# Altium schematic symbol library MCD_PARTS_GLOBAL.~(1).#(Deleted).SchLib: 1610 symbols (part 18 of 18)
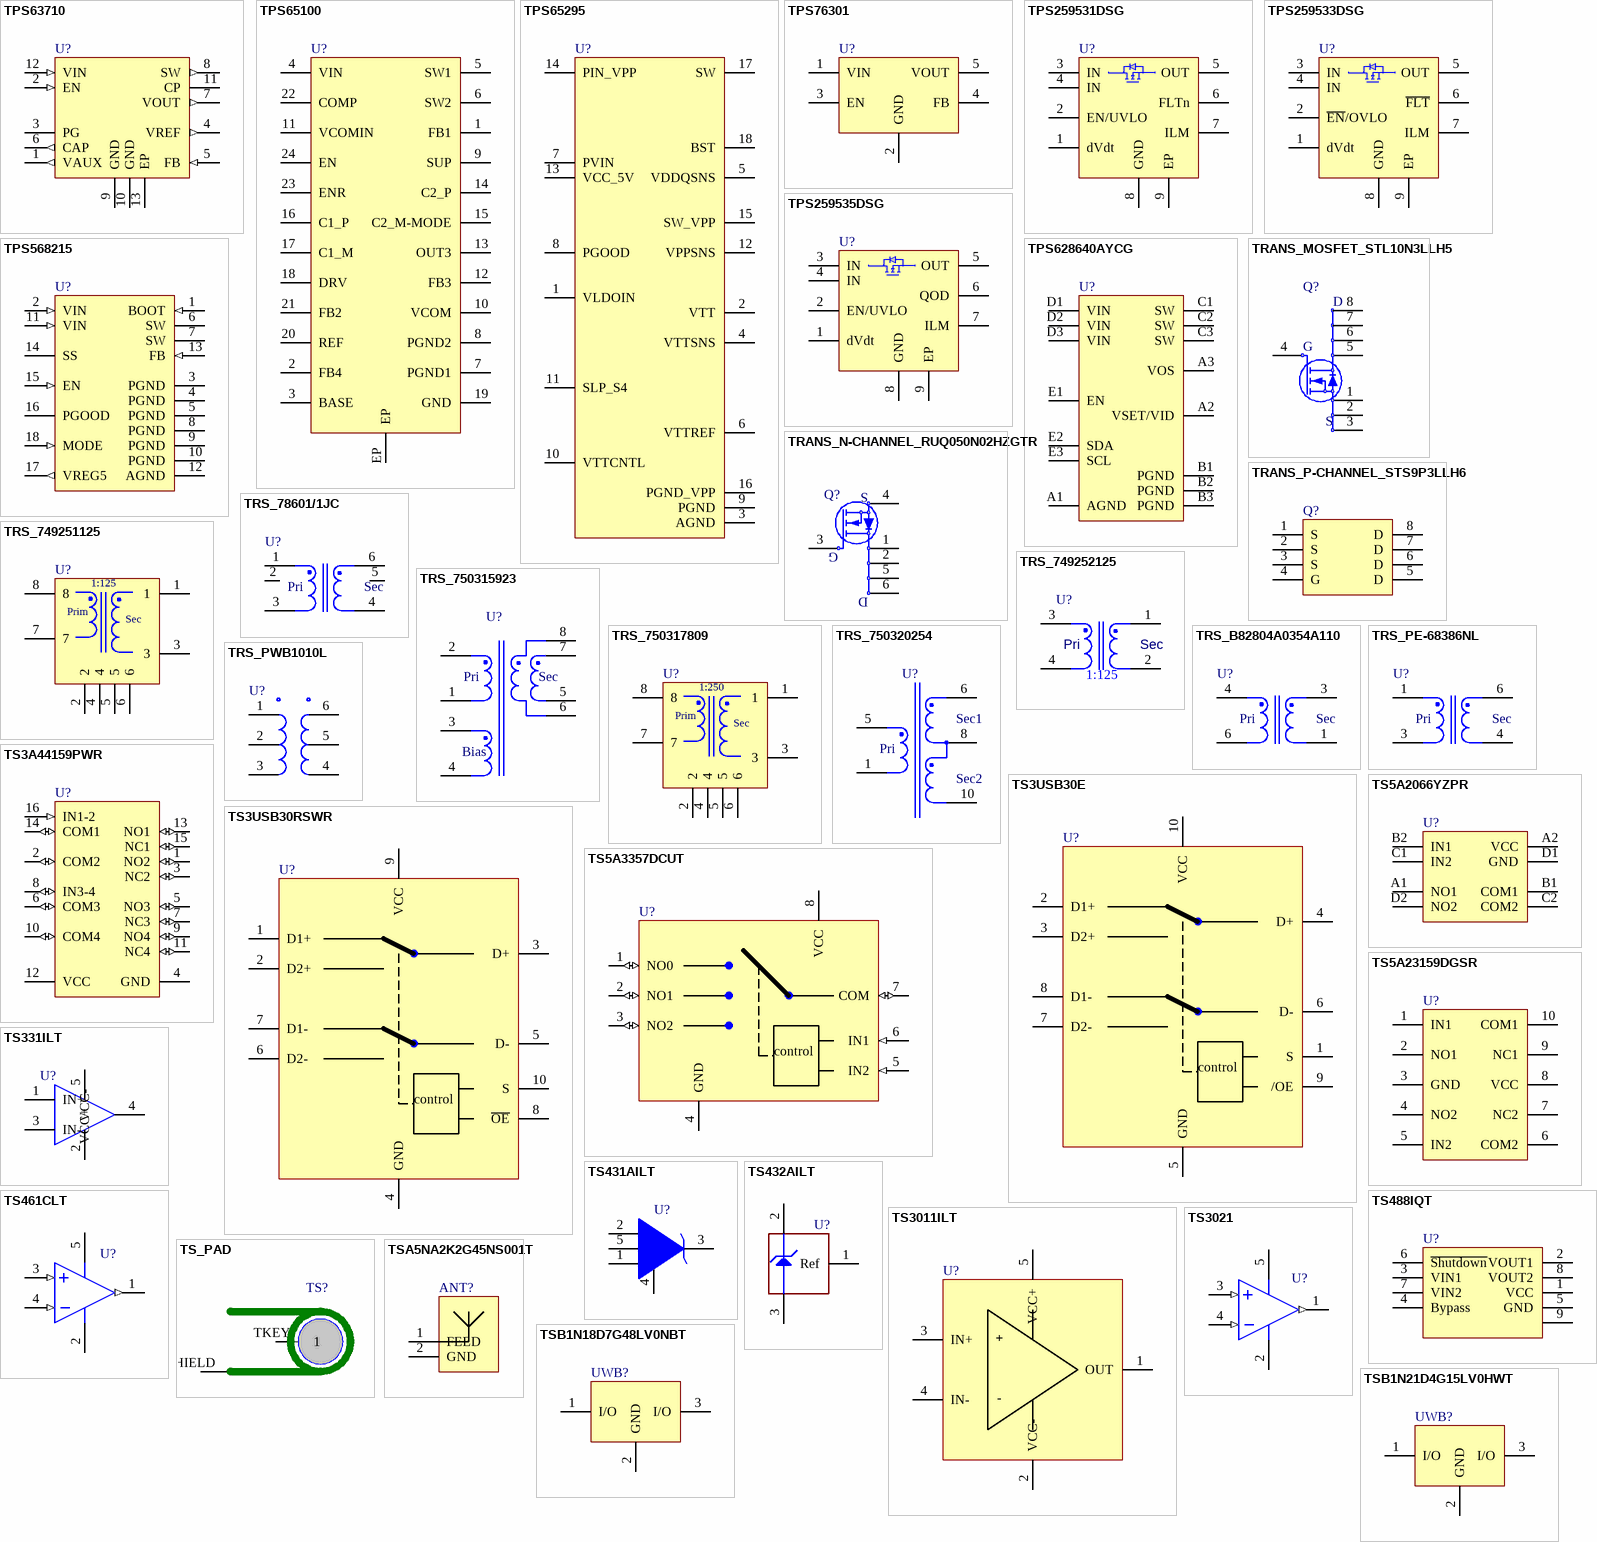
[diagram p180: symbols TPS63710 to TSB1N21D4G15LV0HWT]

## TPS568215
designator U?
pins: 1 BOOT (in), 2 VIN (in), 3 PGND, 4 PGND, 5 PGND, 6 SW, 7 SW, 8 PGND, 9 PGND, 10 PGND, 11 VIN (in), 12 AGND, 13 FB (in), 14 SS, 15 EN (in), 16 PGOOD (oc), 17 VREG5 (out), 18 MODE (in)

## TPS628640AYCG
designator U?
pins: A1 AGND, A2 VSET/VID, A3 VOS, B1 PGND, B2 PGND, B3 PGND, C1 SW, C2 SW, C3 SW, D1 VIN, D2 VIN, D3 VIN, E1 EN, E2 SDA, E3 SCL

## TRANS_MOSFET_STL10N3LLH5
designator Q?
pins: 1, 2, 3, 4, 5, 6, 7, 8

## TRANS_N-CHANNEL_RUQ050N02HZGTR
designator Q?
pins: 1, 2, 3, 4, 5, 6

## TRANS_P-CHANNEL_STS9P3LLH6
designator Q?
pins: 1 S, 2 S, 3 S, 4 G, 5 D, 6 D, 7 D, 8 D

## TRS_78601/1JC
designator U?
pins: 1 P1, 2 P2, 3 P3, 4 S4, 5 S5, 6 S6

## TRS_749251125
designator U?
pins: 1, 2, 3, 4, 5, 6, 7, 8

## TRS_749252125
designator U?
pins: 1 S1, 2 S2, 3 P1, 4 P2

## TRS_750315923
designator U?
pins: 1, 2, 3, 4, 5, 6, 7, 8

## TRS_750317809
designator U?
pins: 1, 2, 3, 4, 5, 6, 7, 8

## TRS_750320254
designator U?
pins: 1 P2, 5 P1, 6 S1, 8 C1, 10 S2

## TRS_B82804A0354A110
designator U?
pins: 1 S2, 3 S1, 4 P1, 6 P2

## TRS_PE-68386NL
designator U?
pins: 1 P1, 3 P2, 4 S2, 6 S1

## TRS_PWB1010L
designator U?
pins: 1, 2, 3, 4, 5, 6

## TS3A44159PWR
designator U?
pins: 1 NO2 (io), 2 COM2 (io), 3 NC2 (io), 4 GND (power), 5 NO3 (io), 6 COM3 (io), 7 NC3 (io), 8 IN3-4 (io), 9 NO4 (io), 10 COM4 (io), 11 NC4 (io), 12 VCC (power), 13 NO1 (io), 14 COM1 (io), 15 NC1 (io), 16 IN1-2 (in)

## TS3USB30E
designator U?
pins: 1 S, 2 D1+, 3 D2+, 4 D+, 5 GND, 6 D-, 7 D2-, 8 D1-, 9 /OE, 10 VCC

## TS3USB30RSWR
designator U?
pins: 1 D1+, 2 D2+, 3 D+, 4 GND, 5 D-, 6 D2-, 7 D1-, 8 ~{OE}, 9 VCC, 10 S

## TS5A2066YZPR
designator U?
pins: A1 NO1, A2 VCC, B1 COM1, B2 IN1, C1 IN2, C2 COM2, D1 GND, D2 NO2

## TS5A3357DCUT
designator U?
pins: 1 NO0 (io), 2 NO1 (io), 3 NO2 (io), 4 GND, 5 IN2 (in), 6 IN1 (in), 7 COM (io), 8 VCC

## TS5A23159DGSR
designator U?
pins: 1 IN1, 2 NO1, 3 GND, 4 NO2, 5 IN2, 6 COM2, 7 NC2, 8 VCC, 9 NC1, 10 COM1

## TS331ILT
designator U?
pins: 1 IN+, 2 VCC-, 3 IN-, 4 OUT, 5 VCC+

## TS431AILT
designator U?
pins: 1 NC, 2 NC, 3 K, 4 REF, 5 A

## TS432AILT
designator U?
pins: 1 Ref, 2 Cathode, 3 Anode

## TS461CLT
designator U?
pins: 1 OUT (out), 2 VDD (power), 3 IN+ (in), 4 IN- (in), 5 VCC (power)

## TS488IQT
designator U?
pins: 1 VCC, 2 VOUT1, 3 VIN1, 4 Bypass, 5 GND, 6 ~{Shutdown}, 7 VIN2, 8 VOUT2, 9 ~{Slug}

## TS3011ILT
designator U?
pins: 1 OUT, 2 VCC-, 3 IN+, 4 IN-, 5 VCC+

## TS3021
designator U?
pins: 1 OUT (out), 2 VDD (power), 3 IN+ (in), 4 IN- (in), 5 VCC (power)

## TS_PAD
designator TS?  (no BOM)
pins: SHIELD 2, TKEY 1

## TSA5NA2K2G45NS001T
designator ANT?
footprint Model Name (Footprint not found)
footprint Model Name (Footprint not found)
pins: 1 FEED, 2 GND

## TSB1N18D7G48LV0NBT
designator UWB?
pins: 1 I/O, 2 GND (power), 3 I/O

## TSB1N21D4G15LV0HWT
designator UWB?
pins: 1 I/O, 2 GND, 3 I/O

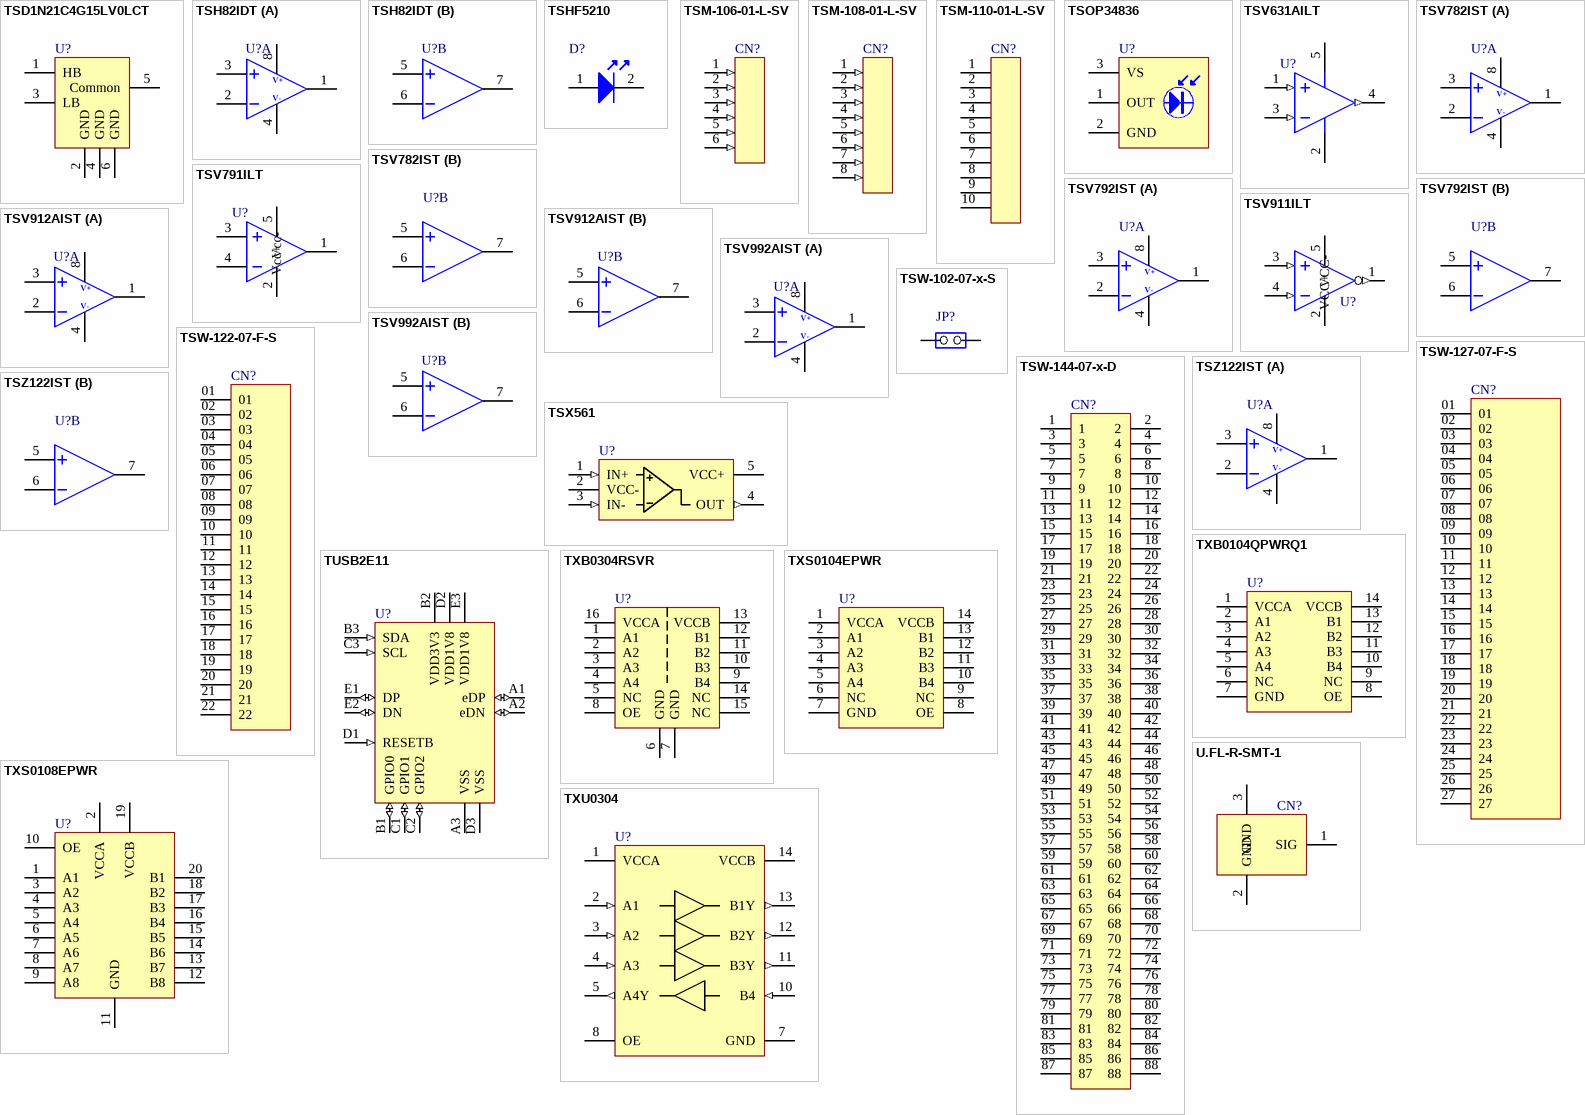
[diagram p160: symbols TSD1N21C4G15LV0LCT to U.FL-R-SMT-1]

## TSD1N21C4G15LV0LCT
designator U?
pins: 1 HB, 2 GND, 3 LB, 4 GND, 5 Common, 6 GND

## TSH82IDT
designator U?
part A pins: 1, 2, 3, 4, 8
part B pins: 5, 6, 7

## TSHF5210
designator D?
pins: 1 A, 2 K

## TSM-106-01-L-SV
designator CN?
pins: 1 (in), 2 (in), 3 (in), 4 (in), 5 (in), 6 (in)

## TSM-108-01-L-SV
designator CN?
pins: 1 (in), 2 (in), 3 (in), 4 (in), 5 (in), 6 (in), 7 (in), 8 (in)

## TSM-110-01-L-SV
designator CN?
pins: 1, 2, 3, 4, 5, 6, 7, 8, 9, 10

## TSOP34836
designator U?
pins: 1 OUT, 2 GND, 3 VS

## TSV631AILT
designator U?
pins: 1 IN+ (in), 2 VDD (power), 3 IN- (in), 4 OUT (out), 5 VCC (power)

## TSV782IST
designator U?
part A pins: 1, 2, 3, 4, 8
part B pins: 5, 6, 7

## TSV791ILT
designator U?
pins: 1 NC hidden, 1, 2 Vcc-, 3, 4, 5 Vcc+

## TSV792IST
designator U?
part A pins: 1, 2, 3, 4, 8
part B pins: 5, 6, 7

## TSV911ILT
designator U?
pins: 1 NC hidden, 1 OUT (out), 2 VCC-, 3 IN+ (in), 4 IN- (in), 5 VCC+

## TSV912AIST
designator U?
part A pins: 1, 2, 3, 4, 8
part B pins: 5, 6, 7

## TSV992AIST
designator U?
part A pins: 1, 2, 3, 4, 8
part B pins: 5, 6, 7

## TSW-102-07-x-S
designator JP?
pins: 1 COMMON, 2 NO

## TSW-122-07-F-S
designator CN?
pins: 01, 02, 03, 04, 05, 06, 07, 08, 09, 10, 11, 12, 13, 14, 15, 16, 17, 18, 19, 20, 21, 22

## TSW-127-07-F-S
designator CN?
pins: 01, 02, 03, 04, 05, 06, 07, 08, 09, 10, 11, 12, 13, 14, 15, 16, 17, 18, 19, 20, 21, 22, 23, 24, 25, 26, 27

## TSW-144-07-x-D
designator CN?
pins: 1, 2, 3, 4, 5, 6, 7, 8, 9, 10, 11, 12, 13, 14, 15, 16, 17, 18, 19, 20, 21, 22, 23, 24, 25, 26, 27, 28, 29, 30, 31, 32, 33, 34, 35, 36, 37, 38, 39, 40, 41, 42, 43, 44, 45, 46, 47, 48, 49, 50, 51, 52, 53, 54, 55, 56, 57, 58, 59, 60, 61, 62, 63, 64, 65, 66, 67, 68, 69, 70, 71, 72, 73, 74, 75, 76, 77, 78, 79, 80, 81, 82, 83, 84, 85, 86, 87, 88

## TSX561
designator U?
pins: 1 IN+ (in), 2 VCC-, 3 IN- (in), 4 OUT (out), 5 VCC+

## TSZ122IST
designator U?
part A pins: 1, 2, 3, 4, 8
part B pins: 5, 6, 7

## TUSB2E11
designator U?
pins: A1 eDP (io), A2 eDN (io), A3 VSS, B1 GPIO0 (io), B2 VDD3V3 (power), B3 SDA (in), C1 GPIO1 (io), C2 GPIO2 (io), C3 SCL (in), D1 RESETB (in), D2 VDD1V8 (power), D3 VSS, E1 DP (io), E2 DN (io), E3 VDD1V8 (power)

## TXB0104QPWRQ1
designator U?
pins: 1 VCCA, 2 A1, 3 A2, 4 A3, 5 A4, 6 NC, 7 GND, 8 OE, 9 NC, 10 B4, 11 B3, 12 B2, 13 B1, 14 VCCB

## TXB0304RSVR
designator U?
pins: 1 A1, 2 A2, 3 A3, 4 A4, 5 NC, 6 GND, 7 GND, 8 OE, 9 B4, 10 B3, 11 B2, 12 B1, 13 VCCB, 14 NC, 15 NC, 16 VCCA

## TXS0104EPWR
designator U?
pins: 1 VCCA, 2 A1, 3 A2, 4 A3, 5 A4, 6 NC, 7 GND, 8 OE, 9 NC, 10 B4, 11 B3, 12 B2, 13 B1, 14 VCCB
1 alternate drawing of the same symbol

## TXS0108EPWR
designator U?
pins: 1 A1, 2 VCCA, 3 A2, 4 A3, 5 A4, 6 A5, 7 A6, 8 A7, 9 A8, 10 OE, 11 GND, 12 B8, 13 B7, 14 B6, 15 B5, 16 B4, 17 B3, 18 B2, 19 VCCB, 20 B1

## TXU0304
designator U?
pins: 1 VCCA (power), 2 A1 (in), 3 A2 (in), 4 A3 (in), 5 A4Y (out), 7 GND (power), 8 OE (oc), 10 B4 (in), 11 B3Y (out), 12 B2Y (out), 13 B1Y (out), 14 VCCB (power)

## U.FL-R-SMT-1
designator CN?
pins: 1 SIG, 2 GND, 3 GND

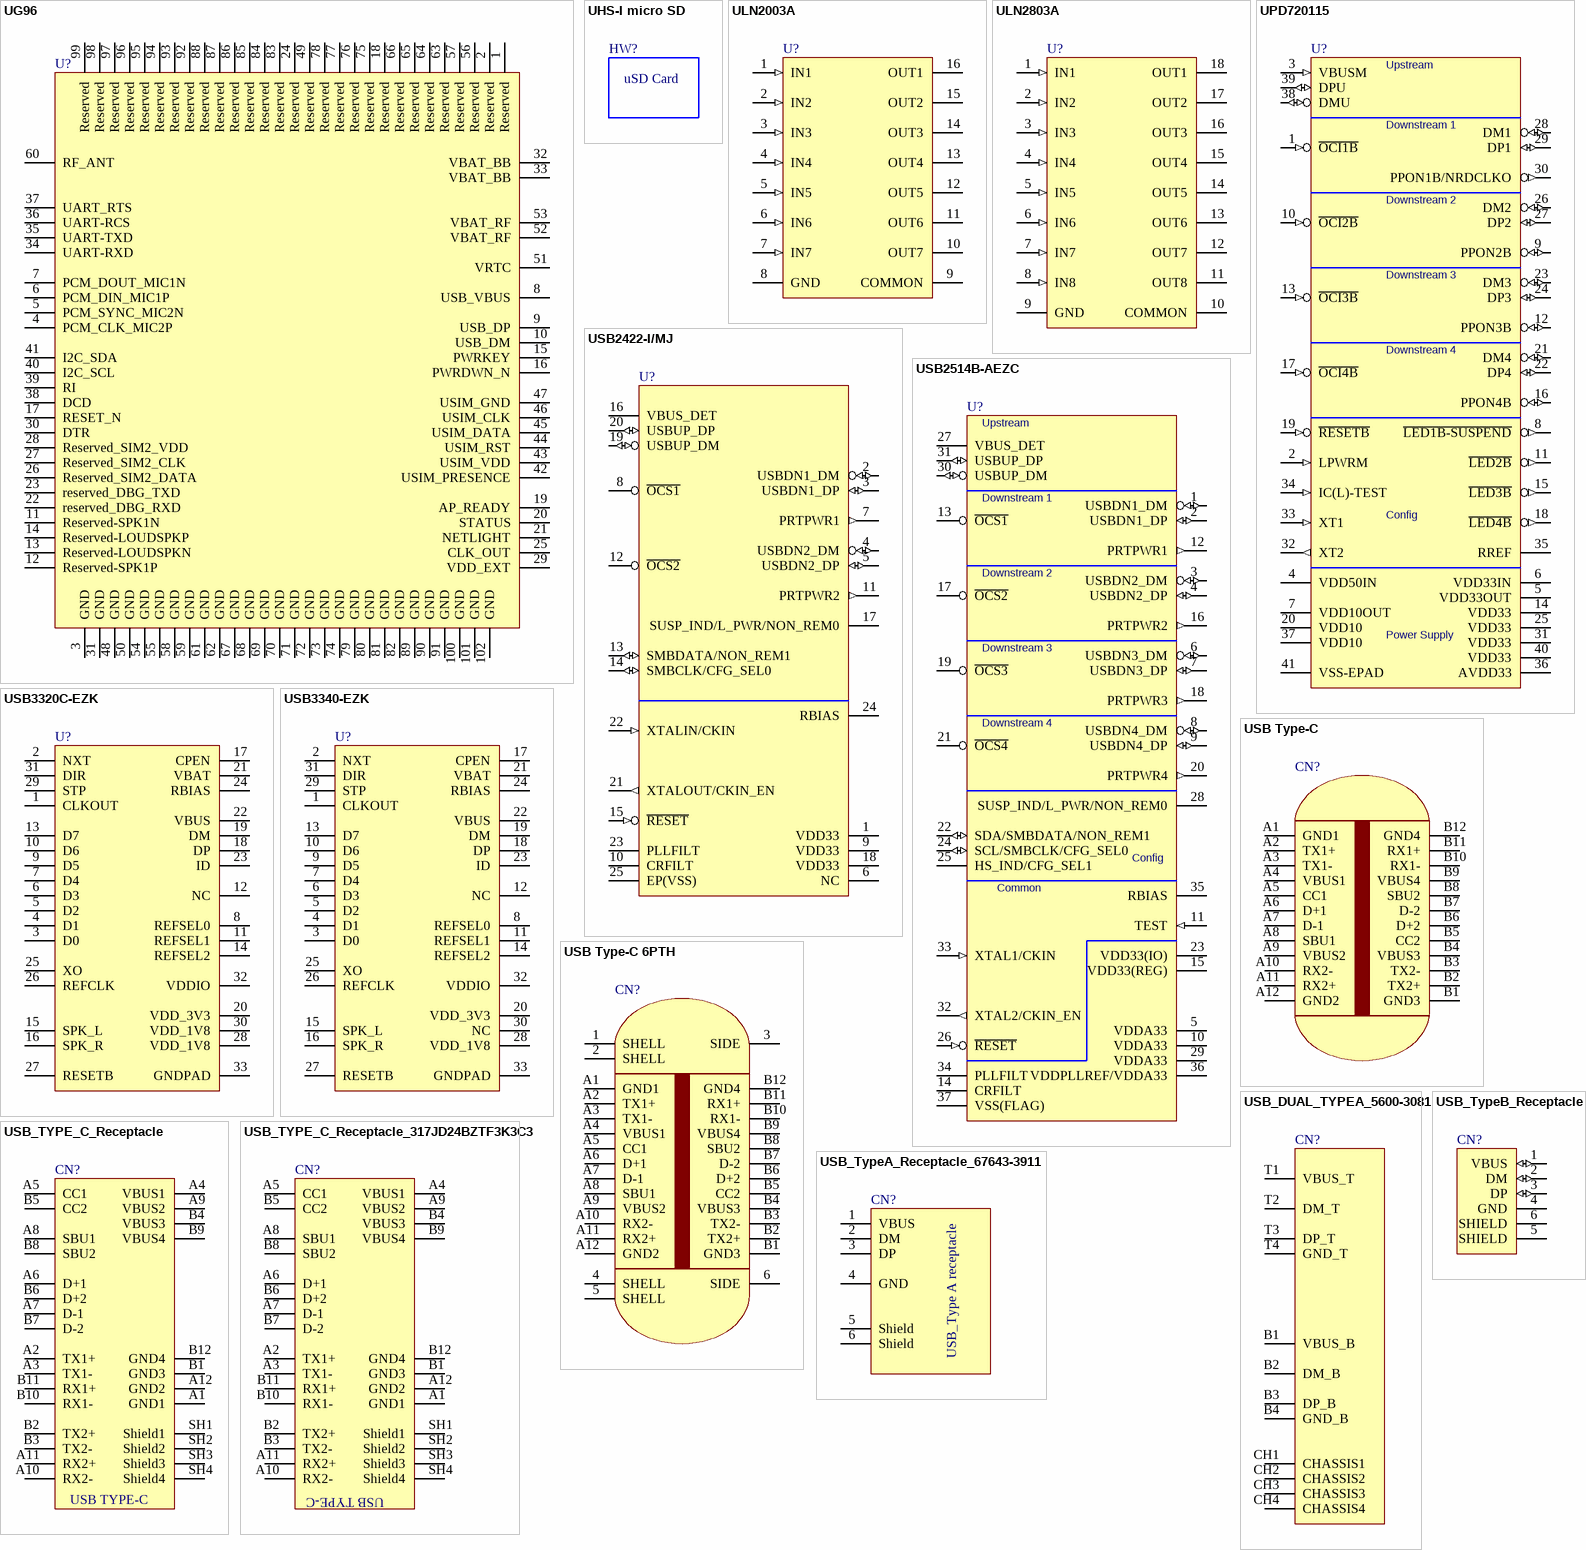
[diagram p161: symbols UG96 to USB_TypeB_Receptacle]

## UG96
designator U?
pins: 1 Reserved, 2 Reserved, 3 GND, 4 PCM_CLK_MIC2P, 5 PCM_SYNC_MIC2N, 6 PCM_DIN_MIC1P, 7 PCM_DOUT_MIC1N, 8 USB_VBUS, 9 USB_DP, 10 USB_DM, 11 Reserved-SPK1N, 12 Reserved-SPK1P, 13 Reserved-LOUDSPKN, 14 Reserved-LOUDSPKP, 15 PWRKEY, 16 PWRDWN_N, 17 RESET_N, 18 Reserved, 19 AP_READY, 20 STATUS, 21 NETLIGHT, 22 reserved_DBG_RXD, 23 reserved_DBG_TXD, 24 Reserved, 25 CLK_OUT, 26 Reserved_SIM2_DATA, 27 Reserved_SIM2_CLK, 28 Reserved_SIM2_VDD, 29 VDD_EXT, 30 DTR, 31 GND, 32 VBAT_BB, 33 VBAT_BB, 34 UART-RXD, 35 UART-TXD, 36 UART-RCS, 37 UART_RTS, 38 DCD, 39 RI, 40 I2C_SCL, 41 I2C_SDA, 42 USIM_PRESENCE, 43 USIM_VDD, 44 USIM_RST, 45 USIM_DATA, 46 USIM_CLK, 47 USIM_GND, 48 GND, 49 Reserved, 50 GND, 51 VRTC, 52 VBAT_RF, 53 VBAT_RF, 54 GND, 55 GND, 56 Reserved, 57 Reserved, 58 GND, 59 GND, 60 RF_ANT, 61 GND, 62 GND, 63 Reserved, 64 Reserved, 65 Reserved, 66 Reserved, 67 GND, 68 GND, 69 GND, 70 GND, 71 GND, 72 GND, 73 GND, 74 GND, 75 Reserved, 76 Reserved, 77 Reserved, 78 Reserved, 79 GND, 80 GND, 81 GND, 82 GND, 83 Reserved, 84 Reserved, 85 Reserved, 86 Reserved, 87 Reserved, 88 Reserved, 89 GND, 90 GND, 91 GND, 92 Reserved, 93 Reserved, 94 Reserved, 95 Reserved, 96 Reserved, 97 Reserved, 98 Reserved, 99 Reserved, 100 GND, 101 GND, 102 GND

## UHS-I micro SD
designator HW?

## ULN2003A
designator U?
pins: 1 IN1 (in), 2 IN2 (in), 3 IN3 (in), 4 IN4 (in), 5 IN5 (in), 6 IN6 (in), 7 IN7 (in), 8 GND (power), 9 COMMON (power), 10 OUT7 (oc), 11 OUT6 (oc), 12 OUT5 (oc), 13 OUT4 (oc), 14 OUT3 (oc), 15 OUT2 (oc), 16 OUT1 (oc)

## ULN2803A
designator U?
pins: 1 IN1 (in), 2 IN2 (in), 3 IN3 (in), 4 IN4 (in), 5 IN5 (in), 6 IN6 (in), 7 IN7 (in), 8 IN8 (in), 9 GND (power), 10 COMMON (power), 11 OUT8 (oc), 12 OUT7 (oc), 13 OUT6 (oc), 14 OUT5 (oc), 15 OUT4 (oc), 16 OUT3 (oc), 17 OUT2 (oc), 18 OUT1 (oc)

## UPD720115
designator U?
pins: 1 ~{OCI1B} (in), 2 LPWRM (in), 3 VBUSM (in), 4 VDD50IN (power), 5 VDD33OUT (power), 6 VDD33IN (power), 7 VDD10OUT (power), 8 ~{LED1B-SUSPEND} (out), 9 PPON2B (io), 10 ~{OCI2B} (in), 11 ~{LED2B} (out), 12 PPON3B (io), 13 ~{OCI3B} (in), 14 VDD33 (power), 15 ~{LED3B} (out), 16 PPON4B (io), 17 ~{OCI4B} (in), 18 ~{LED4B} (out), 19 ~{RESETB} (in), 20 VDD10 (power), 21 DM4 (io), 22 DP4 (io), 23 DM3 (io), 24 DP3 (io), 25 VDD33 (power), 26 DM2 (io), 27 DP2 (io), 28 DM1 (io), 29 DP1 (io), 30 PPON1B/NRDCLKO (out), 31 VDD33 (power), 32 XT2 (out), 33 XT1 (in), 34 IC(L)-TEST (in), 35 RREF, 36 AVDD33 (power), 37 VDD10 (power), 38 DMU (io), 39 DPU (io), 40 VDD33 (power), 41 VSS-EPAD (power)

## USB2422-I/MJ
designator U?
pins: 1 VDD33 (power), 2 USBDN1_DM (io), 3 USBDN1_DP (io), 4 USBDN2_DM (io), 5 USBDN2_DP (io), 6 NC (power), 7 PRTPWR1 (out), 8 ~{OCS1}, 9 VDD33 (power), 10 CRFILT (power), 11 PRTPWR2 (out), 12 ~{OCS2}, 13 SMBDATA/NON_REM1 (io), 14 SMBCLK/CFG_SEL0 (io), 15 ~{RESET} (in), 16 VBUS_DET, 17 SUSP_IND/L_PWR/NON_REM0, 18 VDD33 (power), 19 USBUP_DM (io), 20 USBUP_DP (io), 21 XTALOUT/CKIN_EN (out), 22 XTALIN/CKIN (in), 23 PLLFILT (power), 24 RBIAS, 25 EP(VSS) (power)

## USB2514B-AEZC
designator U?
pins: 1 USBDN1_DM (io), 2 USBDN1_DP (io), 3 USBDN2_DM (io), 4 USBDN2_DP (io), 5 VDDA33 (power), 6 USBDN3_DM (io), 7 USBDN3_DP (io), 8 USBDN4_DM (io), 9 USBDN4_DP (io), 10 VDDA33 (power), 11 TEST (in), 12 PRTPWR1 (out), 13 ~{OCS1}, 14 CRFILT (power), 15 VDD33(REG) (power), 16 PRTPWR2 (out), 17 ~{OCS2}, 18 PRTPWR3 (out), 19 ~{OCS3}, 20 PRTPWR4 (out), 21 ~{OCS4}, 22 SDA/SMBDATA/NON_REM1 (io), 23 VDD33(IO) (power), 24 SCL/SMBCLK/CFG_SEL0 (io), 25 HS_IND/CFG_SEL1, 26 ~{RESET} (in), 27 VBUS_DET, 28 SUSP_IND/L_PWR/NON_REM0, 29 VDDA33 (power), 30 USBUP_DM (io), 31 USBUP_DP (io), 32 XTAL2/CKIN_EN (out), 33 XTAL1/CKIN (in), 34 PLLFILT (power), 35 RBIAS, 36 VDDPLLREF/VDDA33 (power), 37 VSS(FLAG) (power)

## USB3320C-EZK
designator U?
pins: 1 CLKOUT, 2 NXT, 3 D0, 4 D1, 5 D2, 6 D3, 7 D4, 8 REFSEL0, 9 D5, 10 D6, 11 REFSEL1, 12 NC, 13 D7, 14 REFSEL2, 15 SPK_L, 16 SPK_R, 17 CPEN, 18 DP, 19 DM, 20 VDD_3V3, 21 VBAT, 22 VBUS, 23 ID, 24 RBIAS, 25 XO, 26 REFCLK, 27 RESETB, 28 VDD_1V8, 29 STP, 30 VDD_1V8, 31 DIR, 32 VDDIO, 33 GNDPAD

## USB3340-EZK
designator U?
pins: 1 CLKOUT, 2 NXT, 3 D0, 4 D1, 5 D2, 6 D3, 7 D4, 8 REFSEL0, 9 D5, 10 D6, 11 REFSEL1, 12 NC, 13 D7, 14 REFSEL2, 15 SPK_L, 16 SPK_R, 17 CPEN, 18 DP, 19 DM, 20 VDD_3V3, 21 VBAT, 22 VBUS, 23 ID, 24 RBIAS, 25 XO, 26 REFCLK, 27 RESETB, 28 VDD_1V8, 29 STP, 30 NC, 31 DIR, 32 VDDIO, 33 GNDPAD

## USB Type-C
designator CN?
pins: A1 GND1, A2 TX1+, A3 TX1-, A4 VBUS1, A5 CC1, A6 D+1, A7 D-1, A8 SBU1, A9 VBUS2, A10 RX2-, A11 RX2+, A12 GND2, B1 GND3, B2 TX2+, B3 TX2-, B4 VBUS3, B5 CC2, B6 D+2, B7 D-2, B8 SBU2, B9 VBUS4, B10 RX1-, B11 RX1+, B12 GND4

## USB Type-C 6PTH
designator CN?
pins: 1 SHELL, 2 SHELL, 3 SIDE, 4 SHELL, 5 SHELL, 6 SIDE, A1 GND1, A2 TX1+, A3 TX1-, A4 VBUS1, A5 CC1, A6 D+1, A7 D-1, A8 SBU1, A9 VBUS2, A10 RX2-, A11 RX2+, A12 GND2, B1 GND3, B2 TX2+, B3 TX2-, B4 VBUS3, B5 CC2, B6 D+2, B7 D-2, B8 SBU2, B9 VBUS4, B10 RX1-, B11 RX1+, B12 GND4

## USB_DUAL_TYPEA_5600-3081
designator CN?
pins: B1 VBUS_B, B2 DM_B, B3 DP_B, B4 GND_B, CH1 CHASSIS1, CH2 CHASSIS2, CH3 CHASSIS3, CH4 CHASSIS4, T1 VBUS_T, T2 DM_T, T3 DP_T, T4 GND_T

## USB_TYPE_C_Receptacle
designator CN?
pins: A1 GND1, A2 TX1+, A3 TX1-, A4 VBUS1, A5 CC1, A6 D+1, A7 D-1, A8 SBU1, A9 VBUS2, A10 RX2-, A11 RX2+, A12 GND2, B1 GND3, B2 TX2+, B3 TX2-, B4 VBUS3, B5 CC2, B6 D+2, B7 D-2, B8 SBU2, B9 VBUS4, B10 RX1-, B11 RX1+, B12 GND4, SH1 Shield1, SH2 Shield2, SH3 Shield3, SH4 Shield4

## USB_TYPE_C_Receptacle_317JD24BZTF3K3C3
designator CN?
pins: A1 GND1, A2 TX1+, A3 TX1-, A4 VBUS1, A5 CC1, A6 D+1, A7 D-1, A8 SBU1, A9 VBUS2, A10 RX2-, A11 RX2+, A12 GND2, B1 GND3, B2 TX2+, B3 TX2-, B4 VBUS3, B5 CC2, B6 D+2, B7 D-2, B8 SBU2, B9 VBUS4, B10 RX1-, B11 RX1+, B12 GND4, SH1 Shield1, SH2 Shield2, SH3 Shield3, SH4 Shield4

## USB_TypeA_Receptacle_67643-3911
designator CN?
pins: 1 VBUS, 2 DM, 3 DP, 4 GND, 5 Shield, 6 Shield

## USB_TypeB_Receptacle
designator CN?
pins: 1 VBUS (io), 2 DM (io), 3 DP (io), 4 GND, 5 SHIELD (power), 6 SHIELD (power)

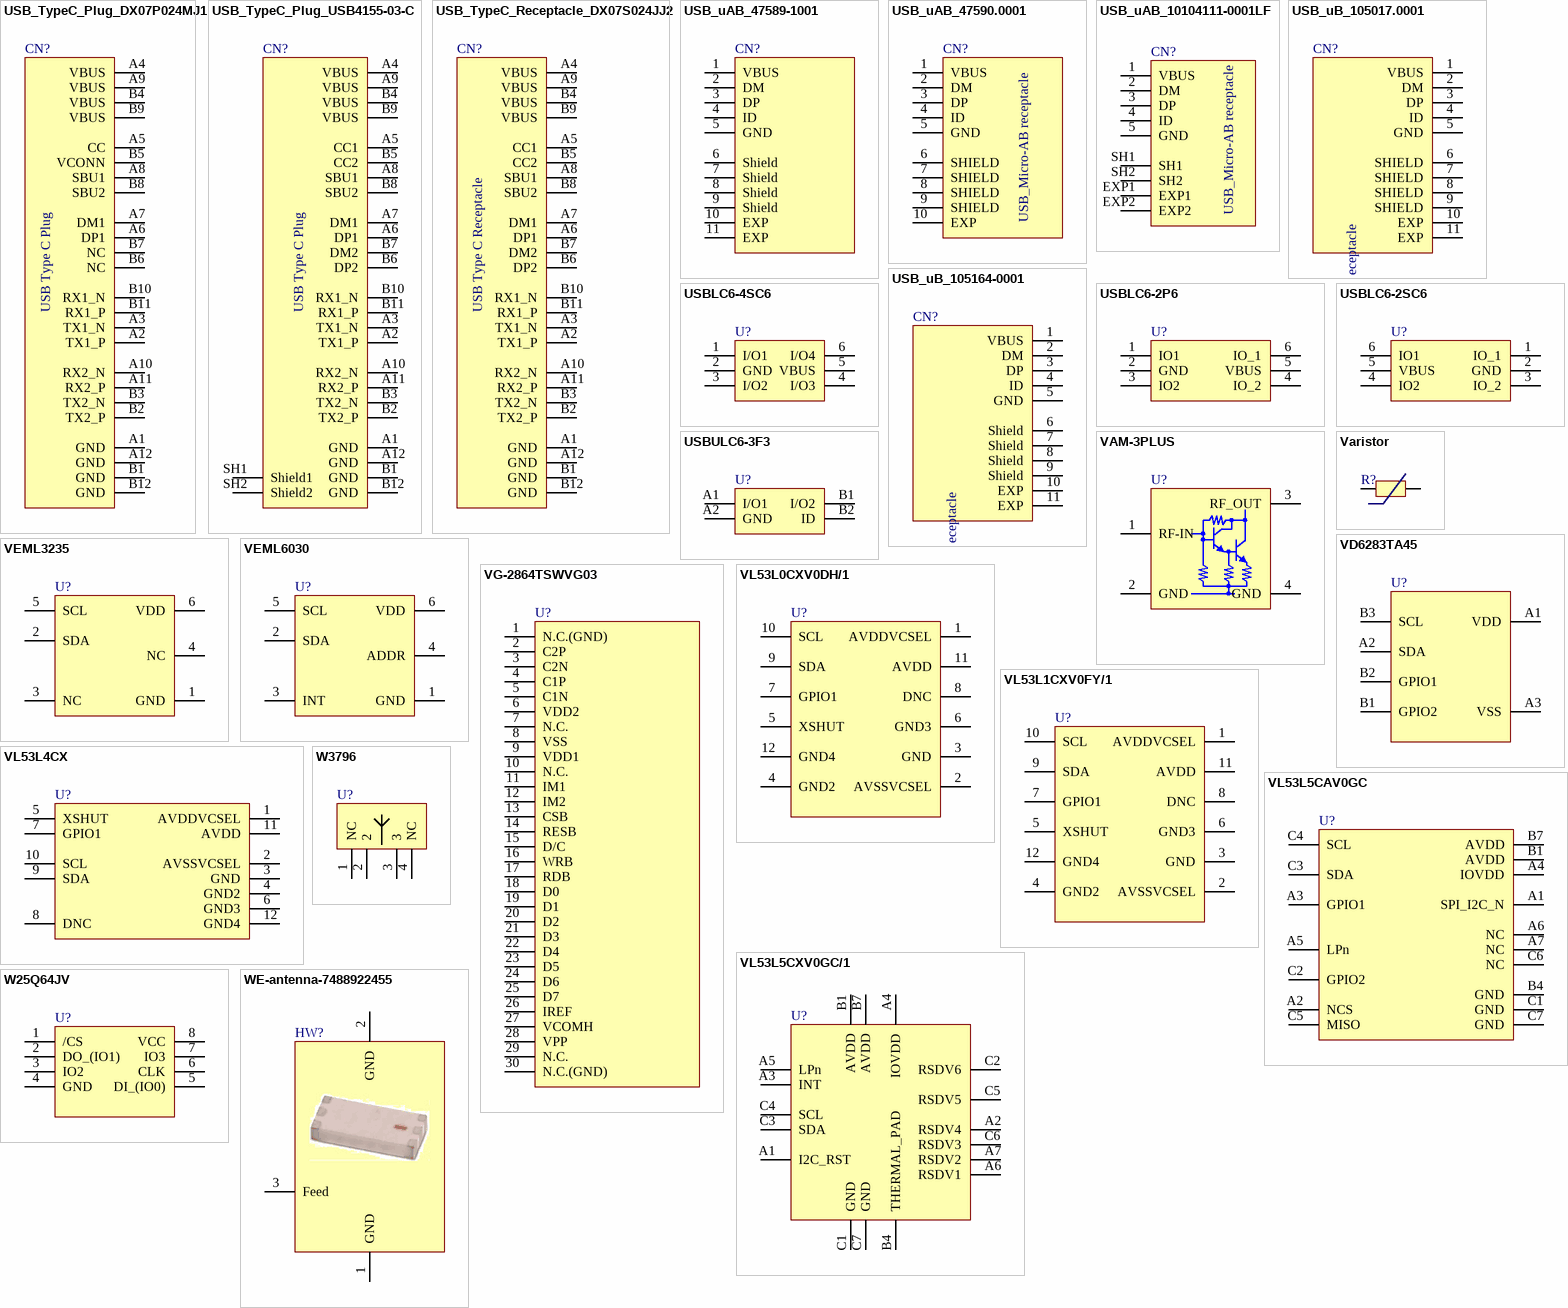
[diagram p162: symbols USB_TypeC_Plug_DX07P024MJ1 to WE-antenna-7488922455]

## USB_TypeC_Plug_DX07P024MJ1
designator CN?
pins: A1 GND, A2 TX1_P, A3 TX1_N, A4 VBUS, A5 CC, A6 DP1, A7 DM1, A8 SBU1, A9 VBUS, A10 RX2_N, A11 RX2_P, A12 GND, B1 GND, B2 TX2_P, B3 TX2_N, B4 VBUS, B5 VCONN, B6 NC, B7 NC, B8 SBU2, B9 VBUS, B10 RX1_N, B11 RX1_P, B12 GND

## USB_TypeC_Plug_USB4155-03-C
designator CN?
pins: A1 GND, A2 TX1_P, A3 TX1_N, A4 VBUS, A5 CC1, A6 DP1, A7 DM1, A8 SBU1, A9 VBUS, A10 RX2_N, A11 RX2_P, A12 GND, B1 GND, B2 TX2_P, B3 TX2_N, B4 VBUS, B5 CC2, B6 DP2, B7 DM2, B8 SBU2, B9 VBUS, B10 RX1_N, B11 RX1_P, B12 GND, SH1 Shield1, SH2 Shield2

## USB_TypeC_Receptacle_DX07S024JJ2
designator CN?
pins: A1 GND, A2 TX1_P, A3 TX1_N, A4 VBUS, A5 CC1, A6 DP1, A7 DM1, A8 SBU1, A9 VBUS, A10 RX2_N, A11 RX2_P, A12 GND, B1 GND, B2 TX2_P, B3 TX2_N, B4 VBUS, B5 CC2, B6 DP2, B7 DM2, B8 SBU2, B9 VBUS, B10 RX1_N, B11 RX1_P, B12 GND

## USB_uAB_47589-1001
designator CN?
pins: 1 VBUS, 2 DM, 3 DP, 4 ID, 5 GND, 6 Shield, 7 Shield, 8 Shield, 9 Shield, 10 EXP, 11 EXP

## USB_uAB_47590.0001
designator CN?
pins: 1 VBUS, 2 DM, 3 DP, 4 ID, 5 GND, 6 SHIELD, 7 SHIELD, 8 SHIELD, 9 SHIELD, 10 EXP

## USB_uAB_10104111-0001LF
designator CN?
pins: 1 VBUS, 2 DM, 3 DP, 4 ID, 5 GND, EXP1, EXP2, SH1, SH2

## USB_uB_105017.0001
designator CN?
pins: 1 VBUS, 2 DM, 3 DP, 4 ID, 5 GND, 6 SHIELD, 7 SHIELD, 8 SHIELD, 9 SHIELD, 10 EXP, 11 EXP

## USB_uB_105164-0001
designator CN?
pins: 1 VBUS, 2 DM, 3 DP, 4 ID, 5 GND, 6 Shield, 7 Shield, 8 Shield, 9 Shield, 10 EXP, 11 EXP

## USBLC6-2P6
designator U?
pins: 1 IO1, 2 GND, 3 IO2, 4 IO_2, 5 VBUS, 6 IO_1

## USBLC6-2SC6
designator U?
pins: 1 IO_1, 2 GND, 3 IO_2, 4 IO2, 5 VBUS, 6 IO1

## USBLC6-4SC6
designator U?
pins: 1 I/O1, 2 GND, 3 I/O2, 4 I/O3, 5 VBUS, 6 I/O4

## USBULC6-3F3
designator U?
pins: A1 I/O1, A2 GND, B1 I/O2, B2 ID

## VAM-3PLUS
designator U?
pins: 1 RF-IN, 2 GND, 3 RF_OUT, 4 GND

## Varistor
designator R?
pins: 1, 2

## VD6283TA45
designator U?
pins: A1 VDD, A2 SDA, A3 VSS, B1 GPIO2, B2 GPIO1, B3 SCL

## VEML3235
designator U?
pins: 1 GND, 2 SDA, 3 NC, 4 NC, 5 SCL, 6 VDD

## VEML6030
designator U?
pins: 1 GND, 2 SDA, 3 INT, 4 ADDR, 5 SCL, 6 VDD

## VG-2864TSWVG03
designator U?
pins: 1 N.C.(GND), 2 C2P, 3 C2N, 4 C1P, 5 C1N, 6 VDD2, 7 N.C., 8 VSS, 9 VDD1, 10 N.C., 11 IM1, 12 IM2, 13 CSB, 14 RESB, 15 D/C, 16 WRB, 17 RDB, 18 D0, 19 D1, 20 D2, 21 D3, 22 D4, 23 D5, 24 D6, 25 D7, 26 IREF, 27 VCOMH, 28 VPP, 29 N.C., 30 N.C.(GND)

## VL53L0CXV0DH/1
designator U?
pins: 1 AVDDVCSEL, 2 AVSSVCSEL, 3 GND, 4 GND2, 5 XSHUT, 6 GND3, 7 GPIO1, 8 DNC, 9 SDA, 10 SCL, 11 AVDD, 12 GND4

## VL53L1CXV0FY/1
designator U?
pins: 1 AVDDVCSEL, 2 AVSSVCSEL, 3 GND, 4 GND2, 5 XSHUT, 6 GND3, 7 GPIO1, 8 DNC, 9 SDA, 10 SCL, 11 AVDD, 12 GND4

## VL53L4CX
designator U?
pins: 1 AVDDVCSEL, 2 AVSSVCSEL, 3 GND, 4 GND2, 5 XSHUT, 6 GND3, 7 GPIO1, 8 DNC, 9 SDA, 10 SCL, 11 AVDD, 12 GND4

## VL53L5CAV0GC
designator U?
pins: A1 SPI_I2C_N, A2 NCS, A3 GPIO1, A4 IOVDD, A5 LPn, A6 NC, A7 NC, B1 AVDD, B4 GND, B7 AVDD, C1 GND, C2 GPIO2, C3 SDA, C4 SCL, C5 MISO, C6 NC, C7 GND

## VL53L5CXV0GC/1
designator U?
pins: A1 I2C_RST, A2 RSDV4, A3 INT, A4 IOVDD, A5 LPn, A6 RSDV1, A7 RSDV2, B1 AVDD, B4 THERMAL_PAD, B7 AVDD, C1 GND, C2 RSDV6, C3 SDA, C4 SCL, C5 RSDV5, C6 RSDV3, C7 GND

## W25Q64JV
designator U?
pins: 1 /CS, 2 DO_(IO1), 3 IO2, 4 GND, 5 DI_(IO0), 6 CLK, 7 IO3, 8 VCC

## W3796
designator U?
pins: 1 NC, 2, 3, 4 NC

## WE-antenna-7488922455
designator HW?
pins: 1 GND, 2 GND, 3 Feed

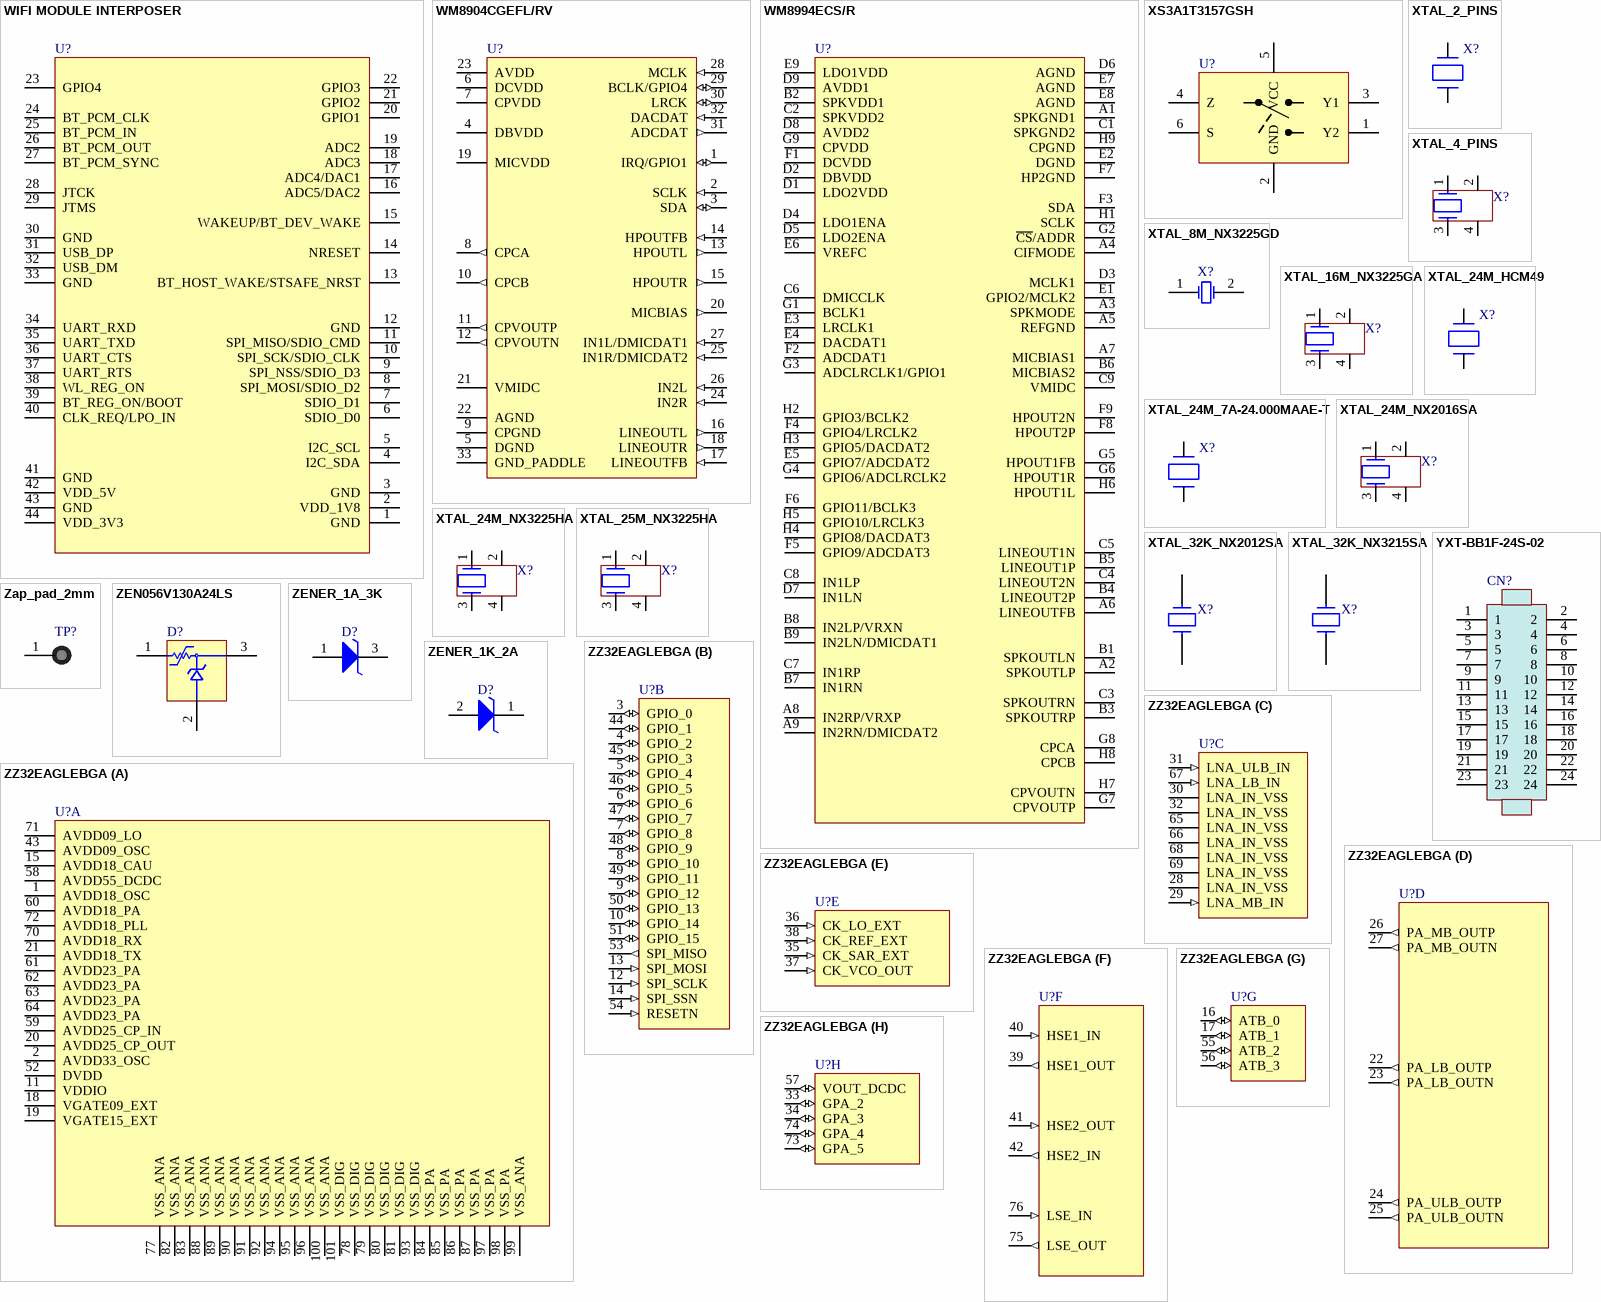
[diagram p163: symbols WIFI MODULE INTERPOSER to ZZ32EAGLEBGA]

## WIFI MODULE INTERPOSER
designator U?
pins: 1 GND, 2 VDD_1V8, 3 GND, 4 I2C_SDA, 5 I2C_SCL, 6 SDIO_D0, 7 SDIO_D1, 8 SPI_MOSI/SDIO_D2, 9 SPI_NSS/SDIO_D3, 10 SPI_SCK/SDIO_CLK, 11 SPI_MISO/SDIO_CMD, 12 GND, 13 BT_HOST_WAKE/STSAFE_NRST, 14 NRESET, 15 WAKEUP/BT_DEV_WAKE, 16 ADC5/DAC2, 17 ADC4/DAC1, 18 ADC3, 19 ADC2, 20 GPIO1, 21 GPIO2, 22 GPIO3, 23 GPIO4, 24 BT_PCM_CLK, 25 BT_PCM_IN, 26 BT_PCM_OUT, 27 BT_PCM_SYNC, 28 JTCK, 29 JTMS, 30 GND, 31 USB_DP, 32 USB_DM, 33 GND, 34 UART_RXD, 35 UART_TXD, 36 UART_CTS, 37 UART_RTS, 38 WL_REG_ON, 39 BT_REG_ON/BOOT, 40 CLK_REQ/LPO_IN, 41 GND, 42 VDD_5V, 43 GND, 44 VDD_3V3

## WM8904CGEFL/RV
designator U?
pins: 1 IRQ/GPIO1 (io), 2 SCLK (in), 3 SDA (io), 4 DBVDD (power), 5 DGND (power), 6 DCVDD (power), 7 CPVDD (power), 8 CPCA (out), 9 CPGND (power), 10 CPCB (out), 11 CPVOUTP (out), 12 CPVOUTN (out), 13 HPOUTL (out), 14 HPOUTFB (in), 15 HPOUTR (out), 16 LINEOUTL (out), 17 LINEOUTFB (in), 18 LINEOUTR (out), 19 MICVDD (power), 20 MICBIAS (out), 21 VMIDC, 22 AGND (power), 23 AVDD (power), 24 IN2R (in), 25 IN1R/DMICDAT2 (in), 26 IN2L (in), 27 IN1L/DMICDAT1 (in), 28 MCLK (in), 29 BCLK/GPIO4 (io), 30 LRCK (io), 31 ADCDAT (out), 32 DACDAT (in), 33 GND_PADDLE (power)

## WM8994ECS/R
designator U?
pins: A1 SPKGND1, A2 SPKOUTLP, A3 SPKMODE, A4 CIFMODE, A5 REFGND, A6 LINEOUTFB, A7 MICBIAS1, A8 IN2RP/VRXP, A9 IN2RN/DMICDAT2, B1 SPKOUTLN, B2 SPKVDD1, B3 SPKOUTRP, B4 LINEOUT2P, B5 LINEOUT1P, B6 MICBIAS2, B7 IN1RN, B8 IN2LP/VRXN, B9 IN2LN/DMICDAT1, C1 SPKGND2, C2 SPKVDD2, C3 SPKOUTRN, C4 LINEOUT2N, C5 LINEOUT1N, C6 DMICCLK, C7 IN1RP, C8 IN1LP, C9 VMIDC, D1 LDO2VDD, D2 DBVDD, D3 MCLK1, D4 LDO1ENA, D5 LDO2ENA, D6 AGND, D7 IN1LN, D8 AVDD2, D9 AVDD1, E1 GPIO2/MCLK2, E2 DGND, E3 LRCLK1, E4 DACDAT1, E5 GPIO7/ADCDAT2, E6 VREFC, E7 AGND, E8 AGND, E9 LDO1VDD, F1 DCVDD, F2 ADCDAT1, F3 SDA, F4 GPIO4/LRCLK2, F5 GPIO9/ADCDAT3, F6 GPIO11/BCLK3, F7 HP2GND, F8 HPOUT2P, F9 HPOUT2N, G1 BCLK1, G2 ~{CS}/ADDR, G3 ADCLRCLK1/GPIO1, G4 GPIO6/ADCLRCLK2, G5 HPOUT1FB, G6 HPOUT1R, G7 CPVOUTP, G8 CPCA, G9 CPVDD, H1 SCLK, H2 GPIO3/BCLK2, H3 GPIO5/DACDAT2, H4 GPIO8/DACDAT3, H5 GPIO10/LRCLK3, H6 HPOUT1L, H7 CPVOUTN, H8 CPCB, H9 CPGND

## XS3A1T3157GSH
designator U?
pins: 1 Y2, 2 GND, 3 Y1, 4 Z, 5 VCC, 6 S

## XTAL_2_PINS
designator X?
pins: 1 X1, 2 X2

## XTAL_4_PINS
designator X?
pins: 1, 2, 3, 4

## XTAL_8M_NX3225GD
designator X?
pins: 1 OSC1, 2 OSC2

## XTAL_16M_NX3225GA
designator X?
pins: 1, 2, 3, 4

## XTAL_24M_7A-24.000MAAE-T
designator X?
pins: 1 X1, 2 X2

## XTAL_24M_HCM49
designator X?
pins: 1 X1, 2 X2

## XTAL_24M_NX2016SA
designator X?
pins: 1, 2, 3, 4

## XTAL_24M_NX3225HA
designator X?
pins: 1, 2, 3, 4

## XTAL_25M_NX3225HA
designator X?
pins: 1, 2, 3, 4

## XTAL_32K_NX2012SA
designator X?
pins: 1, 2

## XTAL_32K_NX3215SA
designator X?
pins: 1, 2

## YXT-BB1F-24S-02
designator CN?
pins: 1, 2, 3, 4, 5, 6, 7, 8, 9, 10, 11, 12, 13, 14, 15, 16, 17, 18, 19, 20, 21, 22, 23, 24

## Zap_pad_2mm
designator TP?
pins: 1

## ZEN056V130A24LS
designator D?
pins: 1, 2, 3

## ZENER_1A_3K
designator D?
pins: 1 A, 3 K

## ZENER_1K_2A
designator D?
pins: 1 K, 2 A

## ZZ32EAGLEBGA
designator U?
part A pins: 1 AVDD18_OSC (power), 2 AVDD33_OSC (power), 11 VDDIO (power), 15 AVDD18_CAU (power), 18 VGATE09_EXT (power), 19 VGATE15_EXT (power), 20 AVDD25_CP_OUT (power), 21 AVDD18_TX (power), 43 AVDD09_OSC (power), 52 DVDD (power), 58 AVDD55_DCDC (power), 59 AVDD25_CP_IN (power), 60 AVDD18_PA (power), 61 AVDD23_PA (power), 62 AVDD23_PA (power), 63 AVDD23_PA (power), 64 AVDD23_PA (power), 70 AVDD18_RX (power), 71 AVDD09_LO (power), 72 AVDD18_PLL (power), 77 VSS_ANA (power), 78 VSS_DIG (power), 79 VSS_DIG (power), 80 VSS_DIG (power), 81 VSS_DIG (power), 82 VSS_ANA (power), 83 VSS_ANA (power), 84 VSS_PA (power), 85 VSS_PA (power), 86 VSS_PA (power), 87 VSS_PA (power), 88 VSS_ANA (power), 89 VSS_ANA (power), 90 VSS_ANA (power), 91 VSS_ANA (power), 92 VSS_ANA (power), 93 VSS_DIG (power), 94 VSS_ANA (power), 95 VSS_ANA (power), 96 VSS_ANA (power), 97 VSS_PA (power), 98 VSS_PA (power), 99 VSS_ANA (power), 100 VSS_ANA (power), 101 VSS_DIG (power)
part B pins: 3 GPIO_0 (io), 4 GPIO_2 (io), 5 GPIO_4 (io), 6 GPIO_6 (io), 7 GPIO_8 (io), 8 GPIO_10 (io), 9 GPIO_12 (io), 10 GPIO_14 (io), 12 SPI_SCLK (in), 13 SPI_MOSI (in), 14 SPI_SSN (in), 44 GPIO_1 (io), 45 GPIO_3 (io), 46 GPIO_5 (io), 47 GPIO_7 (io), 48 GPIO_9 (io), 49 GPIO_11 (io), 50 GPIO_13 (io), 51 GPIO_15 (io), 53 SPI_MISO (out), 54 RESETN (in)
part C pins: 28 LNA_IN_VSS (power), 29 LNA_MB_IN (in), 30 LNA_IN_VSS (power), 31 LNA_ULB_IN (in), 32 LNA_IN_VSS (power), 65 LNA_IN_VSS (power), 66 LNA_IN_VSS (power), 67 LNA_LB_IN (in), 68 LNA_IN_VSS (power), 69 LNA_IN_VSS (power)
part D pins: 22 PA_LB_OUTP (out), 23 PA_LB_OUTN (out), 24 PA_ULB_OUTP (out), 25 PA_ULB_OUTN (out), 26 PA_MB_OUTP (out), 27 PA_MB_OUTN (out)
part E pins: 35 CK_SAR_EXT (in), 36 CK_LO_EXT (in), 37 CK_VCO_OUT (in), 38 CK_REF_EXT (in)
part F pins: 39 HSE1_OUT (out), 40 HSE1_IN (in), 41 HSE2_OUT (in), 42 HSE2_IN (out), 75 LSE_OUT (out), 76 LSE_IN (in)
part G pins: 16 ATB_0 (io), 17 ATB_1 (io), 55 ATB_2 (io), 56 ATB_3 (io)
part H pins: 33 GPA_2 (io), 34 GPA_3 (io), 57 VOUT_DCDC (io), 73 GPA_5 (io), 74 GPA_4 (io)
1 alternate drawing of the same symbol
